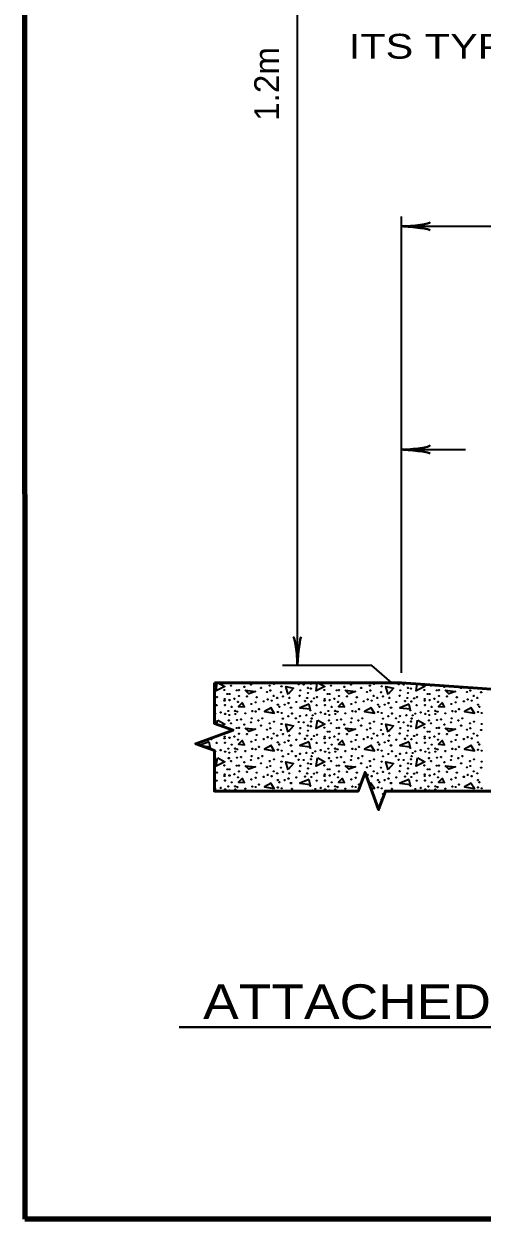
# Model space of a CAD drawing. Extents: x -105 to 751, y -65 to 479.
# Drawn here: x -47.6 to 7.8, y -53.4 to 91.1 of the extents above; entities that cross this region are included whole.
import ezdxf
from ezdxf.enums import TextEntityAlignment as Align

# ---------------------------------------------------------------- set-up
doc = ezdxf.new("R2010")
doc.units = 0
doc.header["$LTSCALE"] = 1.2
doc.layers.add('1', color=7, linetype='Continuous', lineweight=35)

msp = doc.modelspace()

# ---------------------------------------------------------------- linework, layer by layer
at = {"layer": '1'}
for p, q in [((-14.497, 13.539), (-14.497, 151.048)), ((-1.897, 12.639), (-1.897, 67.839)), ((-1.897, 39.639), (5.83, 39.639)), ((-24.25, 6.436), (-24.178, 6.936)), ((-25.186, 4.32), (-26.262, 3.885)), ((-5.578, -0.696), (-5.798, -0.816))]:
    msp.add_line(p, q, dxfattribs=at)
at = {"layer": '1', "lineweight": 40}
msp.add_line((-28.776, -30.174), (183.047, -30.174), dxfattribs=at)
at = {"layer": '1', "lineweight": 158}
msp.add_line((744.128, -53.4), (-47.472, -53.4), dxfattribs=at)
msp.add_lwpolyline([(744.128, 472.7), (-47.572, 472.6), (-47.472, -53.4)], dxfattribs=at)
at = {"layer": '1'}
for points in [[(-1.897, 66.639), (54.365, 66.639), (105.725, 66.639)], [(-3.097, 11.439), (-5.497, 13.539), (-16.297, 13.539)], [(-24.072, 11.439), (-23.29, 10.992), (-24.322, 10.488), (-24.186, 11.439)], [(-15.61, 10.032), (-15.898, 10.992), (-14.962, 10.8), (-15.634, 10.08)], [(-11.976, 11.439), (-11.194, 10.992), (-12.226, 10.488), (-12.09, 11.439)], [(-3.514, 10.032), (-3.802, 10.992), (-2.866, 10.8), (-3.538, 10.08)], [(0.401, 11.278), (0.902, 10.992), (-0.13, 10.488), (-0.013, 11.307)], [(-21.154, 9.048), (-21.61, 8.568), (-20.914, 8.52), (-21.154, 9)], [(-13.09, 8.88), (-14.218, 8.424), (-12.97, 8.28), (-13.09, 8.832)], [(-9.058, 9.048), (-9.514, 8.568), (-8.818, 8.52), (-9.058, 9)], [(-0.994, 8.88), (-2.122, 8.424), (-0.874, 8.28), (-0.994, 8.832)], [(3.038, 9.048), (2.582, 8.568), (3.278, 8.52), (3.038, 9)], [(-17.674, 8.424), (-18.466, 7.992), (-17.29, 7.776), (-17.722, 8.448)], [(-5.578, 8.424), (-6.37, 7.992), (-5.194, 7.776), (-5.626, 8.448)], [(6.518, 8.424), (5.726, 7.992), (6.902, 7.776), (6.47, 8.448)], [(-24.13, 6.912), (-23.29, 6.432), (-23.695, 6.234)], [(-15.61, 5.472), (-15.898, 6.432), (-14.962, 6.24), (-15.634, 5.52)], [(-12.034, 6.912), (-11.194, 6.432), (-12.226, 5.928), (-12.082, 6.936)], [(-3.514, 5.472), (-3.802, 6.432), (-2.866, 6.24), (-3.538, 5.52)], [(0.062, 6.912), (0.902, 6.432), (-0.13, 5.928), (0.014, 6.936)], [(-21.154, 4.488), (-21.61, 4.008), (-20.914, 3.96), (-21.154, 4.44)], [(-9.058, 4.488), (-9.514, 4.008), (-8.818, 3.96), (-9.058, 4.44)], [(3.038, 4.488), (2.582, 4.008), (3.278, 3.96), (3.038, 4.44)], [(-26.153, 3.845), (-25.066, 3.72), (-25.186, 4.272)], [(-17.674, 3.864), (-18.466, 3.432), (-17.29, 3.216), (-17.722, 3.888)], [(-13.09, 4.32), (-14.218, 3.864), (-12.97, 3.72), (-13.09, 4.272)], [(-5.578, 3.864), (-6.37, 3.432), (-5.194, 3.216), (-5.626, 3.888)], [(-0.994, 4.32), (-2.122, 3.864), (-0.874, 3.72), (-0.994, 4.272)], [(6.518, 3.864), (5.726, 3.432), (6.902, 3.216), (6.47, 3.888)], [(-24.13, 2.352), (-23.29, 1.872), (-24.322, 1.368), (-24.178, 2.376)], [(-15.61, 0.912), (-15.898, 1.872), (-14.962, 1.68), (-15.634, 0.96)], [(-12.034, 2.352), (-11.194, 1.872), (-12.226, 1.368), (-12.082, 2.376)], [(-3.514, 0.912), (-3.802, 1.872), (-2.866, 1.68), (-3.538, 0.96)], [(0.062, 2.352), (0.902, 1.872), (-0.13, 1.368), (0.014, 2.376)], [(-21.154, -0.072), (-21.61, -0.552), (-20.914, -0.6), (-21.154, -0.12)], [(-17.674, -0.696), (-18.466, -1.128), (-17.29, -1.344), (-17.722, -0.672)], [(-13.09, -0.24), (-14.218, -0.696), (-12.97, -0.84), (-13.09, -0.288)], [(-9.058, -0.072), (-9.514, -0.552), (-8.818, -0.6), (-9.058, -0.12)], [(-5.635, -1.263), (-5.194, -1.344), (-5.626, -0.672)], [(-0.994, -0.24), (-2.122, -0.696), (-0.874, -0.84), (-0.994, -0.288)], [(3.038, -0.072), (2.582, -0.552), (3.278, -0.6), (3.038, -0.12)], [(6.518, -0.696), (5.726, -1.128), (6.902, -1.344), (6.47, -0.672)]]:
    msp.add_lwpolyline(points, dxfattribs=at)
at = {"layer": '1', "lineweight": 53}
for points in [[(-24.539, 11.439), (-1.897, 11.439), (54.365, 7.504), (56.673, 29.462)], [(120.627, -1.64), (45.627, -1.64), (44.806, -3.895), (43.165, 0.615), (42.344, -1.64), (-3.856, -1.64), (-4.677, -3.895), (-6.318, 0.615), (-7.139, -1.64), (-24.539, -1.64), (-24.539, 3.258), (-26.794, 4.079), (-22.284, 5.72), (-24.539, 6.541), (-24.539, 11.439)]]:
    msp.add_lwpolyline(points, dxfattribs=at)
at = {"layer": '1'}
for points in [[(-20.818, 10.536), (-19.57, 10.392), (-20.386, 10.104)], [(-8.722, 10.536), (-7.474, 10.392), (-8.29, 10.104)], [(3.374, 10.536), (4.622, 10.392), (3.806, 10.104)], [(-20.818, 5.976), (-19.57, 5.832), (-20.386, 5.544)], [(-8.722, 5.976), (-7.474, 5.832), (-8.29, 5.544)], [(3.374, 5.976), (4.622, 5.832), (3.806, 5.544)], [(-20.818, 1.416), (-19.57, 1.272), (-20.386, 0.984)], [(-8.722, 1.416), (-7.474, 1.272), (-8.29, 0.984)], [(3.374, 1.416), (4.622, 1.272), (3.806, 0.984)]]:
    msp.add_lwpolyline(points, close=True, dxfattribs=at)
for centre in [(-23.347, 10.574), (-22.949, 10.097), (-22.679, 10.097), (-22.52, 11.099), (-21.843, 10.54), (-21.572, 10.558), (-20.92, 10.956), (-20.109, 11.226), (-18.884, 10.829), (-18.169, 10.336), (-17.835, 11.099), (-17.787, 10.511), (-17.342, 11.306), (-16.467, 10.304), (-16.419, 11.02), (-14.352, 11.258), (-14.161, 10.526), (-13.732, 11.226), (-13.223, 10.829), (-13.207, 10.208), (-12.873, 10.749), (-12.857, 11.322), (-11.251, 10.574), (-10.853, 10.097), (-10.583, 10.097), (-10.424, 11.099), (-9.747, 10.54), (-9.476, 10.558), (-8.824, 10.956), (-8.013, 11.226), (-6.788, 10.829), (-6.073, 10.336), (-5.739, 11.099), (-5.691, 10.511), (-5.246, 11.306), (-4.371, 10.304), (-4.323, 11.02), (-2.256, 11.258), (-2.065, 10.526), (-1.636, 11.226), (-1.127, 10.829), (-1.111, 10.208), (-0.777, 10.749), (-0.761, 11.322), (0.845, 10.574), (1.243, 10.097), (1.513, 10.097), (1.672, 11.099), (2.349, 10.54), (2.62, 10.558), (3.272, 10.956), (5.308, 10.829), (6.023, 10.336), (6.405, 10.511), (7.725, 10.304), (-24.269, 8.735), (-24.237, 9.715), (-23.315, 9.291), (-23.299, 9.492), (-23.267, 8.75), (-22.71, 9.355), (-22.122, 9.508), (-21.683, 9.132), (-21.572, 9.842), (-20.602, 9.795), (-20.077, 8.878), (-19.536, 9.084), (-19.409, 9.699), (-18.566, 9.196), (-18.089, 9.429), (-17.612, 9.275), (-17.373, 9.858), (-16.944, 9.62), (-16.865, 8.798), (-16.244, 9.795), (-16.053, 8.798), (-15.576, 8.989), (-15.465, 9.62), (-14.638, 9.116), (-14.24, 9.874), (-13.572, 9.228), (-13.318, 9.604), (-12.809, 9.18), (-12.475, 9.572), (-12.173, 8.735), (-12.141, 9.715), (-11.219, 9.291), (-11.203, 9.492), (-11.171, 8.75), (-10.614, 9.355), (-10.026, 9.508), (-9.587, 9.132), (-9.476, 9.842), (-8.506, 9.795), (-7.981, 8.878), (-7.44, 9.084), (-7.313, 9.699), (-6.47, 9.196), (-5.993, 9.429), (-5.516, 9.275), (-5.277, 9.858), (-4.848, 9.62), (-4.769, 8.798), (-4.148, 9.795), (-3.957, 8.798), (-3.48, 8.989), (-3.369, 9.62), (-2.542, 9.116), (-2.144, 9.874), (-1.476, 9.228), (-1.222, 9.604), (-0.713, 9.18), (-0.379, 9.572), (-0.077, 8.735), (-0.045, 9.715), (0.877, 9.291), (0.893, 9.492), (0.925, 8.75), (1.482, 9.355), (2.07, 9.508), (2.509, 9.132), (2.62, 9.842), (3.59, 9.795), (4.115, 8.878), (4.656, 9.084), (4.783, 9.699), (5.626, 9.196), (6.103, 9.429), (6.58, 9.275), (6.819, 9.858), (7.248, 9.62), (7.327, 8.798), (-24.412, 7.716), (-23.776, 7.86), (-23.235, 7.685), (-22.854, 8.035), (-22.726, 7.557), (-22.456, 8.528), (-22.026, 8.05), (-22.011, 7.669), (-21.747, 7.955), (-20.809, 7.748), (-19.95, 8.019), (-19.536, 7.971), (-19.155, 8.257), (-16.865, 7.907), (-16.674, 8.544), (-16.403, 7.796), (-15.608, 7.398), (-15.306, 8.432), (-15.242, 8.432), (-15.163, 7.732), (-14.193, 7.414), (-13.413, 7.526), (-12.936, 8.114), (-12.65, 7.51), (-12.316, 7.716), (-11.68, 7.86), (-11.139, 7.685), (-10.758, 8.035), (-10.63, 7.557), (-10.36, 8.528), (-9.93, 8.05), (-9.915, 7.669), (-9.651, 7.955), (-8.713, 7.748), (-7.854, 8.019), (-7.44, 7.971), (-7.059, 8.257), (-4.769, 7.907), (-4.578, 8.544), (-4.307, 7.796), (-3.512, 7.398), (-3.21, 8.432), (-3.146, 8.432), (-3.067, 7.732), (-2.097, 7.414), (-1.317, 7.526), (-0.84, 8.114), (-0.554, 7.51), (-0.22, 7.716), (0.416, 7.86), (0.957, 7.685), (1.338, 8.035), (1.466, 7.557), (1.736, 8.528), (2.166, 8.05), (2.181, 7.669), (2.445, 7.955), (3.383, 7.748), (4.242, 8.019), (4.656, 7.971), (5.037, 8.257), (7.327, 7.907), (7.518, 8.544), (7.789, 7.796), (-22.79, 6.889), (-22.52, 6.539), (-21.843, 5.98), (-21.82, 6.953), (-21.572, 5.998), (-21.318, 7.016), (-20.92, 6.396), (-20.109, 6.666), (-20.045, 7.144), (-19.218, 6.889), (-18.884, 6.269), (-18.741, 7.144), (-18.169, 5.776), (-17.835, 6.539), (-17.787, 5.951), (-17.342, 6.746), (-16.419, 6.46), (-16.26, 7.112), (-14.686, 7.144), (-14.352, 6.698), (-14.161, 5.966), (-13.732, 6.666), (-13.223, 6.269), (-12.873, 6.189), (-12.857, 6.762), (-12.777, 7.128), (-11.251, 6.014), (-10.694, 6.889), (-10.424, 6.539), (-9.747, 5.98), (-9.724, 6.953), (-9.476, 5.998), (-9.222, 7.016), (-8.824, 6.396), (-8.013, 6.666), (-7.949, 7.144), (-7.122, 6.889), (-6.788, 6.269), (-6.645, 7.144), (-6.073, 5.776), (-5.739, 6.539), (-5.691, 5.951), (-5.246, 6.746), (-4.323, 6.46), (-4.164, 7.112), (-2.59, 7.144), (-2.256, 6.698), (-2.065, 5.966), (-1.636, 6.666), (-1.127, 6.269), (-0.777, 6.189), (-0.761, 6.762), (-0.681, 7.128), (0.845, 6.014), (1.402, 6.889), (1.672, 6.539), (2.349, 5.98), (2.372, 6.953), (2.62, 5.998), (2.874, 7.016), (3.272, 6.396), (4.083, 6.666), (4.147, 7.144), (4.974, 6.889), (5.308, 6.269), (5.451, 7.144), (6.023, 5.776), (6.357, 6.539), (6.405, 5.951), (6.85, 6.746), (7.773, 6.46), (-24.905, 4.62), (-23.315, 4.731), (-23.299, 4.932), (-22.71, 4.795), (-22.679, 5.537), (-22.122, 4.948), (-21.683, 4.572), (-21.572, 5.282), (-20.602, 5.235), (-20.077, 4.318), (-19.536, 4.524), (-19.409, 5.139), (-18.566, 4.636), (-18.089, 4.869), (-17.612, 4.715), (-17.373, 5.298), (-16.944, 5.06), (-16.467, 5.744), (-16.244, 5.235), (-15.576, 4.429), (-15.465, 5.06), (-14.638, 4.556), (-14.24, 5.314), (-13.572, 4.668), (-13.318, 5.044), (-13.207, 5.648), (-12.809, 4.62), (-12.475, 5.012), (-12.141, 5.155), (-11.219, 4.731), (-11.203, 4.932), (-10.853, 5.537), (-10.614, 4.795), (-10.583, 5.537), (-10.026, 4.948), (-9.587, 4.572), (-9.476, 5.282), (-8.506, 5.235), (-7.981, 4.318), (-7.44, 4.524), (-7.313, 5.139), (-6.47, 4.636), (-5.993, 4.869), (-5.516, 4.715), (-5.277, 5.298), (-4.848, 5.06), (-4.371, 5.744), (-4.148, 5.235), (-3.48, 4.429), (-3.369, 5.06), (-2.542, 4.556), (-2.144, 5.314), (-1.476, 4.668), (-1.222, 5.044), (-1.111, 5.648), (-0.713, 4.62), (-0.379, 5.012), (-0.045, 5.155), (0.877, 4.731), (0.893, 4.932), (1.243, 5.537), (1.482, 4.795), (1.513, 5.537), (2.07, 4.948), (2.509, 4.572), (2.62, 5.282), (3.59, 5.235), (4.115, 4.318), (4.656, 4.524), (4.783, 5.139), (5.626, 4.636), (6.103, 4.869), (6.58, 4.715), (6.819, 5.298), (7.248, 5.06), (7.725, 5.744), (-25.032, 3.554), (-24.412, 3.156), (-24.269, 4.175), (-23.776, 3.3), (-23.267, 4.19), (-23.235, 3.125), (-22.854, 3.475), (-22.726, 2.997), (-22.456, 3.968), (-22.026, 3.49), (-22.011, 3.109), (-21.747, 3.395), (-20.809, 3.188), (-19.95, 3.459), (-19.536, 3.411), (-19.155, 3.697), (-16.865, 4.238), (-16.865, 3.347), (-16.674, 3.984), (-16.403, 3.236), (-16.053, 4.238), (-15.306, 3.872), (-15.242, 3.872), (-15.163, 3.172), (-13.413, 2.966), (-12.936, 3.554), (-12.65, 2.95), (-12.316, 3.156), (-12.173, 4.175), (-11.68, 3.3), (-11.171, 4.19), (-11.139, 3.125), (-10.758, 3.475), (-10.63, 2.997), (-10.36, 3.968), (-9.93, 3.49), (-9.915, 3.109), (-9.651, 3.395), (-8.713, 3.188), (-7.854, 3.459), (-7.44, 3.411), (-7.059, 3.697), (-4.769, 4.238), (-4.769, 3.347), (-4.578, 3.984), (-4.307, 3.236), (-3.957, 4.238), (-3.21, 3.872), (-3.146, 3.872), (-3.067, 3.172), (-1.317, 2.966), (-0.84, 3.554), (-0.554, 2.95), (-0.22, 3.156), (-0.077, 4.175), (0.416, 3.3), (0.925, 4.19), (0.957, 3.125), (1.338, 3.475), (1.466, 2.997), (1.736, 3.968), (2.166, 3.49), (2.181, 3.109), (2.445, 3.395), (3.383, 3.188), (4.242, 3.459), (4.656, 3.411), (5.037, 3.697), (7.327, 4.238), (7.327, 3.347), (7.518, 3.984), (7.789, 3.236), (-23.347, 1.454), (-22.79, 2.329), (-22.52, 1.979), (-21.843, 1.42), (-21.82, 2.393), (-21.572, 1.438), (-21.318, 2.456), (-20.92, 1.836), (-20.109, 2.106), (-20.045, 2.584), (-19.218, 2.329), (-18.884, 1.709), (-18.741, 2.584), (-17.835, 1.979), (-17.342, 2.186), (-16.419, 1.9), (-16.26, 2.552), (-15.608, 2.838), (-14.686, 2.584), (-14.352, 2.138), (-14.193, 2.854), (-13.732, 2.106), (-13.223, 1.709), (-12.873, 1.629), (-12.857, 2.202), (-12.777, 2.568), (-11.251, 1.454), (-10.694, 2.329), (-10.424, 1.979), (-9.747, 1.42), (-9.724, 2.393), (-9.476, 1.438), (-9.222, 2.456), (-8.824, 1.836), (-8.013, 2.106), (-7.949, 2.584), (-7.122, 2.329), (-6.788, 1.709), (-6.645, 2.584), (-5.739, 1.979), (-5.246, 2.186), (-4.323, 1.9), (-4.164, 2.552), (-3.512, 2.838), (-2.59, 2.584), (-2.256, 2.138), (-2.097, 2.854), (-1.636, 2.106), (-1.127, 1.709), (-0.777, 1.629), (-0.761, 2.202), (-0.681, 2.568), (0.845, 1.454), (1.402, 2.329), (1.672, 1.979), (2.349, 1.42), (2.372, 2.393), (2.62, 1.438), (2.874, 2.456), (3.272, 1.836), (4.083, 2.106), (4.147, 2.584), (4.974, 2.329), (5.308, 1.709), (5.451, 2.584), (6.357, 1.979), (6.85, 2.186), (7.773, 1.9), (-24.237, 0.595), (-23.315, 0.171), (-23.299, 0.372), (-22.949, 0.977), (-22.71, 0.235), (-22.679, 0.977), (-22.122, 0.388), (-21.683, 0.012), (-21.572, 0.722), (-20.602, 0.675), (-19.409, 0.579), (-18.566, 0.076), (-18.169, 1.216), (-18.089, 0.309), (-17.787, 1.391), (-17.612, 0.155), (-17.373, 0.738), (-16.944, 0.5), (-16.467, 1.184), (-16.244, 0.675), (-15.465, 0.5), (-14.638, -0.004), (-14.24, 0.754), (-14.161, 1.406), (-13.572, 0.108), (-13.318, 0.484), (-13.207, 1.088), (-12.809, 0.06), (-12.475, 0.452), (-12.141, 0.595), (-11.219, 0.171), (-11.203, 0.372), (-10.853, 0.977), (-10.614, 0.235), (-10.583, 0.977), (-10.026, 0.388), (-9.587, 0.012), (-9.476, 0.722), (-8.506, 0.675), (-7.313, 0.579), (-6.073, 1.216), (-5.993, 0.309), (-5.691, 1.391), (-5.516, 0.155), (-5.277, 0.738), (-4.848, 0.5), (-4.371, 1.184), (-4.148, 0.675), (-3.369, 0.5), (-2.542, -0.004), (-2.144, 0.754), (-2.065, 1.406), (-1.476, 0.108), (-1.222, 0.484), (-1.111, 1.088), (-0.713, 0.06), (-0.379, 0.452), (-0.045, 0.595), (0.877, 0.171), (0.893, 0.372), (1.243, 0.977), (1.482, 0.235), (1.513, 0.977), (2.07, 0.388), (2.509, 0.012), (2.62, 0.722), (3.59, 0.675), (4.783, 0.579), (5.626, 0.076), (6.023, 1.216), (6.103, 0.309), (6.405, 1.391), (6.58, 0.155), (6.819, 0.738), (7.248, 0.5), (7.725, 1.184), (-24.412, -1.404), (-24.269, -0.385), (-23.776, -1.26), (-23.267, -0.37), (-23.235, -1.435), (-22.854, -1.085), (-22.456, -0.592), (-22.026, -1.07), (-22.011, -1.451), (-21.747, -1.165), (-20.809, -1.372), (-20.077, -0.242), (-19.95, -1.101), (-19.536, -0.036), (-19.536, -1.149), (-19.155, -0.863), (-16.865, -0.322), (-16.865, -1.213), (-16.674, -0.576), (-16.403, -1.324), (-16.053, -0.322), (-15.576, -0.131), (-15.306, -0.688), (-15.242, -0.688), (-15.163, -1.388), (-12.936, -1.006), (-12.316, -1.404), (-12.173, -0.385), (-11.68, -1.26), (-11.171, -0.37), (-11.139, -1.435), (-10.758, -1.085), (-10.36, -0.592), (-9.93, -1.07), (-9.915, -1.451), (-9.651, -1.165), (-8.713, -1.372), (-7.981, -0.242), (-7.854, -1.101), (-7.44, -0.036), (-7.44, -1.149), (-7.059, -0.863), (-4.769, -0.322), (-4.769, -1.213), (-4.578, -0.576), (-4.307, -1.324), (-3.957, -0.322), (-3.48, -0.131), (-3.21, -0.688), (-3.146, -0.688), (-3.067, -1.388), (-0.84, -1.006), (-0.22, -1.404), (-0.077, -0.385), (0.416, -1.26), (0.925, -0.37), (0.957, -1.435), (1.338, -1.085), (1.736, -0.592), (2.166, -1.07), (2.181, -1.451), (2.445, -1.165), (3.383, -1.372), (4.115, -0.242), (4.242, -1.101), (4.656, -0.036), (4.656, -1.149), (5.037, -0.863), (7.327, -0.322), (7.327, -1.213), (7.518, -0.576), (7.789, -1.324), (-22.726, -1.563), (-13.413, -1.594), (-10.63, -1.563), (-4.323, -2.66), (-4.164, -2.008), (-1.317, -1.594), (1.466, -1.563)]:
    msp.add_circle(centre, 0.0318, dxfattribs=at)
for centre, start, end in [((-22.79, 11.449), 199.24152, 340.75848), ((-19.218, 11.449), 199.24152, 340.75848), ((-10.694, 11.449), 199.24152, 340.75848), ((-7.122, 11.449), 199.24152, 340.75848), ((-12.65, -1.61), 290.25809, 249.74191), ((-5.246, -2.374), 316.97271, 83.02533), ((-0.554, -1.61), 290.25809, 249.74191)]:
    msp.add_arc(centre, 0.0318, start, end, dxfattribs=at)
at = {"layer": '1', "lineweight": 40}
for centre, major_axis, ratio, start_param, end_param in [((-0.553, 66.385), (-2.108, 0.211), 0.07063, 3.1407148, 5.41811), ((-0.553, 66.385), (-2.108, 0.211), 0.07063, 3.1407148, 5.41811), ((-0.588, 66.97), (-2.143, -0.187), 0.122415, 0.8963533, 3.1415927), ((-0.588, 66.97), (-2.143, -0.187), 0.122415, 0.8963533, 3.1415927), ((-0.553, 39.385), (-2.108, 0.211), 0.07063, 3.1407148, 5.41811), ((-0.588, 39.97), (-2.143, -0.187), 0.122415, 0.8963533, 3.1415927), ((-14.829, 14.848), (0.187, -2.143), 0.122415, 0.8963533, 3.1415927), ((-14.829, 14.848), (0.187, -2.143), 0.122415, 0.8963533, 3.1415927), ((-14.243, 14.883), (-0.211, -2.108), 0.07063, 3.1407148, 5.41811), ((-14.243, 14.883), (-0.211, -2.108), 0.07063, 3.1407148, 5.41811)]:
    msp.add_ellipse(centre, major_axis=major_axis, ratio=ratio, start_param=start_param, end_param=end_param, dxfattribs=at)

# ---------------------------------------------------------------- texts
at = {"layer": '1', "width": 1.25}
msp.add_text('ITS TYPE "B" BRACKET. ', height=3, dxfattribs=at).set_placement((-8.291, 86.909))
at = {"layer": '1'}
msp.add_text('1.2m', height=3, rotation=90, dxfattribs=at).set_placement((-16.713, 79.392))
at = {"layer": '1', "width": 1.15}
msp.add_text('ATTACHED TO ROADWAY SIDE OF RECTANGULAR TUBE RAILING', height=4.2, dxfattribs=at).set_placement((76.915, -29.214), align=Align.CENTER)

doc.saveas('drawing.dxf')
